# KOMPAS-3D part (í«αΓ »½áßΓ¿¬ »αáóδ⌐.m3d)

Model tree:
1. Эскиз:1
2. Операция выдавливания:1
     Расстояние 1 = 2
3. Эскиз:4
4. Операция выдавливания:3
     Расстояние 1 = 2
5. Эскиз:5
6. Вырезать элемент выдавливания:2
     Расстояние 1 = 4

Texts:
  борт пластик правый
  stalker61
  Полипропилен  ГОСТ 26996-86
